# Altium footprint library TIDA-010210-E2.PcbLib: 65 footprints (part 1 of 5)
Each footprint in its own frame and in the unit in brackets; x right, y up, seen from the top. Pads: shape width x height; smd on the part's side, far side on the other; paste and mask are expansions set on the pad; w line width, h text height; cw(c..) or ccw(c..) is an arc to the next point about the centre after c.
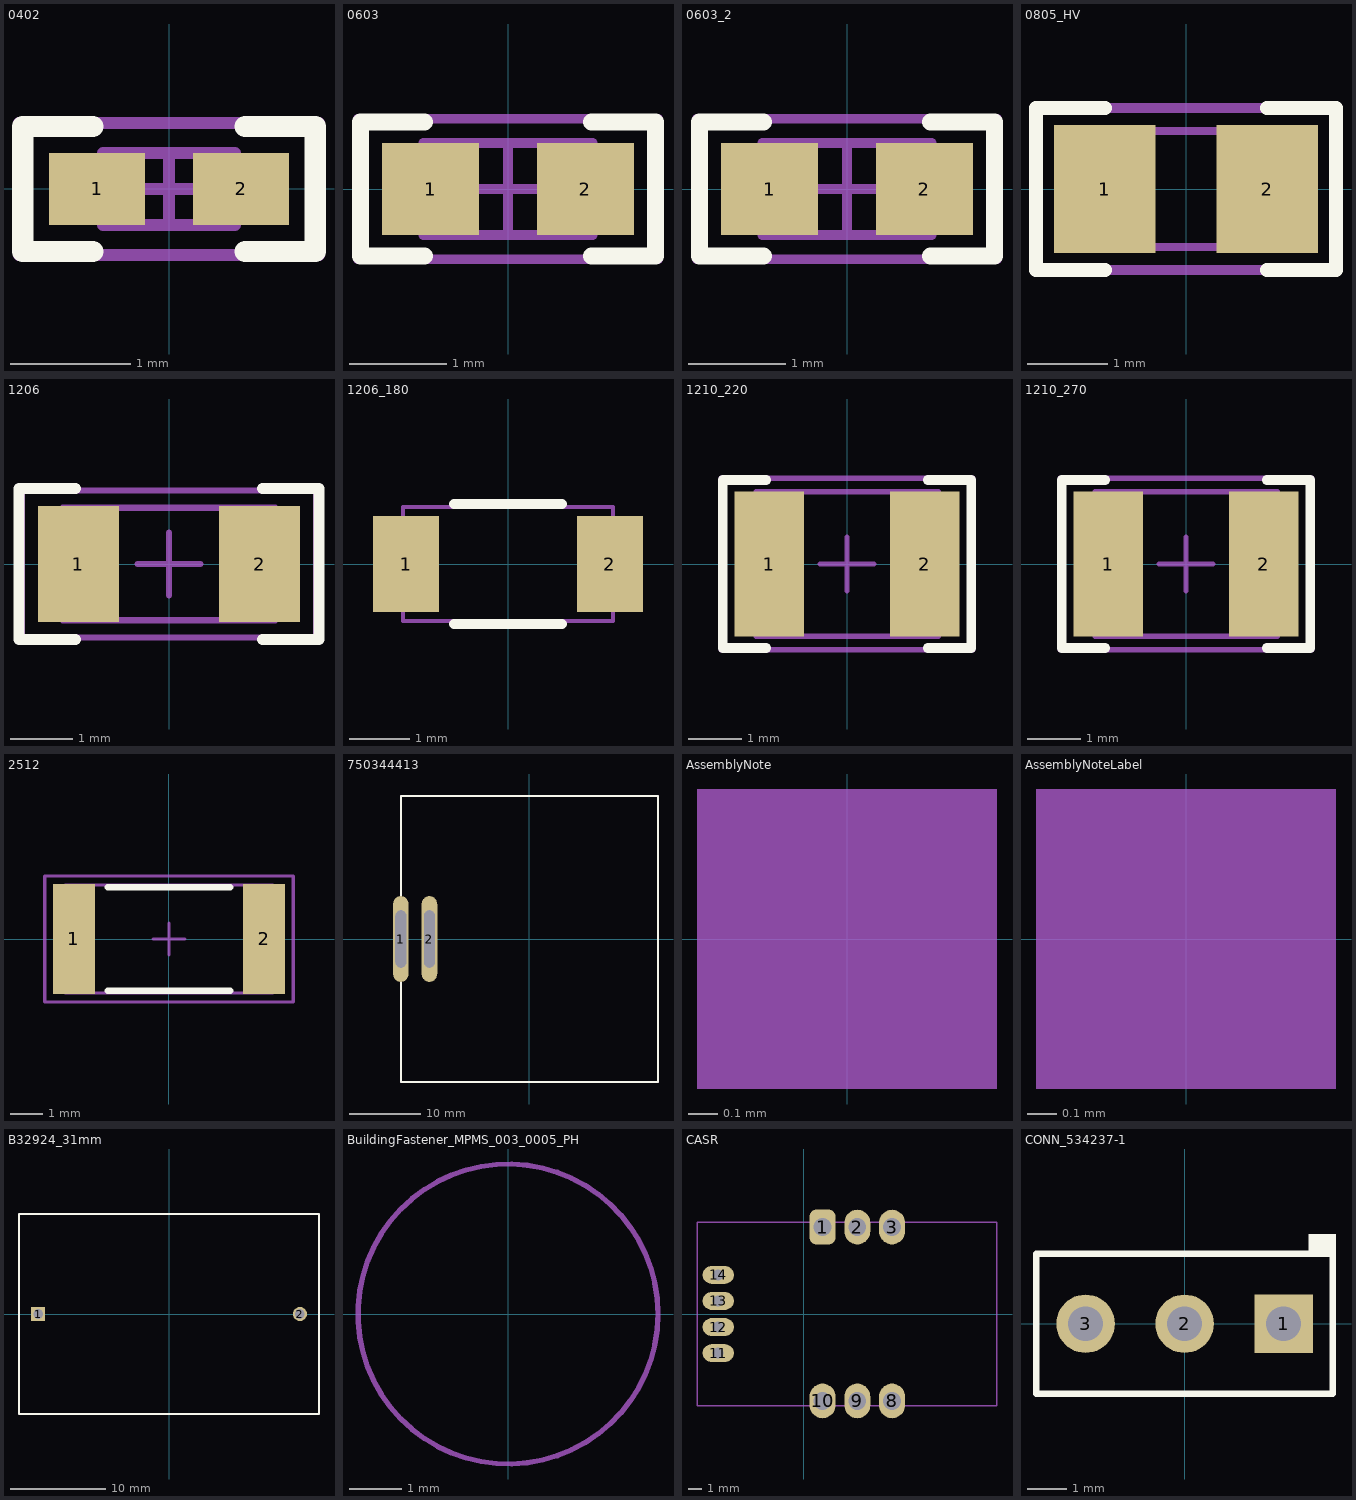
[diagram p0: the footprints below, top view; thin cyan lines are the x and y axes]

## 0402 [mm] "0402 from SM-752 data"
height 0.6
pads (2):
  rect 0.8x0.6 smd: 1(-0.6,0) 2(0.6,0)
Top Overlay:
  lines w0.178: -0.635,-0.521 -1.219,-0.521 -1.219,0.521 -0.635,0.521 ; 0.635,-0.521 1.219,-0.521 1.219,0.521 0.635,0.521
Mechanical 5:
  lines w0.1: -1.25,-0.55 1.25,-0.55 1.25,0.55 -1.25,0.55 -1.25,-0.55
  text ".Designator" at -1.117,-0.305 h0.61
Mechanical 13:
  lines w0.1: -0.35,-0.3 -0.35,0.3 ; 0.35,-0.3 0.35,0.3 ; -0.55,-0.3 -0.55,0.3 0.55,0.3 0.55,-0.3 -0.55,-0.3
Mechanical 15:
  lines w0.1: -0.3,0 0.3,0 ; 0,-0.3 0,0.3 ; -1.25,-0.55 -1.25,0.55 1.25,0.55 1.25,-0.55 -1.25,-0.55
3D body: height 0.6, standoff 0, extent -0.549,-0.299 -0.351,0.299
3D body: height 0.6, standoff 0, extent -0.349,-0.299 0.349,0.299
3D body: height 0.6, standoff 0, extent 0.351,-0.299 0.549,0.299

## 0603 [mm] "0603 from SM-752 data"
height 1
pads (2):
  rect 1x0.95 smd: 1(-0.8,0) 2(0.8,0)
Top Overlay:
  lines w0.178: -0.864,-0.691 -1.524,-0.691 -1.524,0.693 -0.864,0.693 ; 0.864,-0.691 1.524,-0.691 1.524,0.693 0.864,0.693
Mechanical 5:
  lines w0.1: -1.55,-0.725 -1.55,0.725 1.55,0.725 1.55,-0.725 -1.55,-0.725
  text ".Designator" at -1.397,-0.381 h0.76
Mechanical 13:
  lines w0.1: -0.55,-0.475 -0.55,0.475 ; 0.55,-0.475 0.55,0.475 ; -0.875,-0.475 0.875,-0.475 0.875,0.475 -0.875,0.475 -0.875,-0.475
Mechanical 15:
  lines w0.1: -0.475,0 0.475,0 ; 0,-0.475 0,0.475 ; -1.55,-0.725 1.55,-0.725 1.55,0.725 -1.55,0.725 -1.55,-0.725
3D body: height 1, standoff 0, extent -0.874,-0.474 -0.551,0.474
3D body: height 1, standoff 0, extent -0.549,-0.474 0.549,0.474
3D body: height 1, standoff 0, extent 0.551,-0.474 0.874,0.474

## 0603_2 [mm]
pads (2):
  rect 1x0.95 smd: 1(-0.8,0) 2(0.8,0)
Top Overlay:
  lines w0.178: -0.864,-0.691 -1.524,-0.691 -1.524,0.693 -0.864,0.693 ; 0.864,-0.691 1.524,-0.691 1.524,0.693 0.864,0.693
Mechanical 5:
  lines w0.1: -1.55,-0.725 -1.55,0.725 1.55,0.725 1.55,-0.725 -1.55,-0.725
  text ".Designator" at -1.397,-0.381 h0.76
Mechanical 13:
  lines w0.1: -0.55,-0.475 -0.55,0.475 ; 0.55,-0.475 0.55,0.475 ; -0.875,-0.475 0.875,-0.475 0.875,0.475 -0.875,0.475 -0.875,-0.475
Mechanical 15:
  lines w0.1: -0.475,0 0.475,0 ; 0,-0.475 0,0.475 ; -1.55,-0.725 1.55,-0.725 1.55,0.725 -1.55,0.725 -1.55,-0.725
3D body: height 1, standoff 0, extent -0.874,-0.474 -0.551,0.474
3D body: height 1, standoff 0, extent -0.549,-0.474 0.549,0.474
3D body: height 1, standoff 0, extent 0.551,-0.474 0.874,0.474

## 0805_HV [mil] "0805 with 30mil clearance between pads"
height 57.09
pads (2):
  rect 50x63 smd: 1(-40,0) 2(40,0)
Top Overlay:
  lines w7: -40,-40 -74,-40 -74,0 -74,40 -40,40 ; 40,-40 74,-40 74,0 74,40 40,40
Mechanical 5:
  lines w5: -74,-40 -74,40 74,40 74,-40 -74,-40
  text ".Designator" at -64,-17 h35
Mechanical 13:
  lines w3.94: -25.59,-28.54 -25.59,28.54 ; 25.59,-28.54 25.59,28.54 ; -43.31,-28.54 -43.31,28.54 43.31,28.54 43.31,-28.54 -43.31,-28.54
3D body: height 57.09, standoff 0, extent 25.61,-28.52 43.29,28.52
3D body: height 57.09, standoff 0, extent -25.57,-28.52 25.57,28.52
3D body: height 57.09, standoff 0, extent -43.29,-28.52 -25.61,28.52

## 1206 [mm] "1206 from SM-752 data"
height 1.35
pads (2):
  rect 1.3x1.85 smd: 1(-1.45,0) 2(1.45,0)
Top Overlay:
  lines w0.178: -1.5,-1.21 -2.4,-1.21 -2.4,1.21 -1.5,1.21 ; 1.5,-1.21 2.4,-1.21 2.4,1.21 1.5,1.21
Mechanical 5:
  lines w0.1: -1.7,-0.9 -1.7,0.9 1.7,0.9 1.7,-0.9 -1.7,-0.9
  text ".Designator" at -1.475,-0.4 h0.81
Mechanical 13:
  lines w0.1: -1.2,-0.9 -1.2,0.9 ; 1.2,-0.9 1.2,0.9 ; -1.7,-0.9 -1.7,0.9 1.7,0.9 1.7,-0.9 -1.7,-0.9
Mechanical 15:
  lines w0.1: -0.5,0 0.5,0 ; 0,-0.5 0,0.5 ; -2.35,-1.175 -2.35,1.175 2.35,1.175 2.35,-1.175 -2.35,-1.175
3D body: height 1.35, standoff 0, extent 1.201,-0.899 1.699,0.899
3D body: height 1.35, standoff 0, extent -1.199,-0.899 1.199,0.899
3D body: height 1.35, standoff 0, extent -1.699,-0.899 -1.201,0.899

## 1206_180 [mm] "1206_180"
height 1.8
pads (2):
  rect 1.1x1.6 smd: 1(-1.7,0) 2(1.7,0)
Top Overlay:
  lines w0.17: -0.9,-1 0.9,-1 ; -0.9,1 0.9,1
Mechanical 5:
  lines w0.07: -1.75,-0.95 1.75,-0.95 1.75,0.95 -1.75,0.95 -1.75,-0.95
  text ".Designator" at -1.5,-0.4 h0.81
3D body: height 1.8, standoff 0, extent -1.749,-0.949 -1.301,0.949
3D body: height 1.8, standoff 0, extent -1.299,-0.949 1.299,0.949
3D body: height 1.8, standoff 0, extent 1.301,-0.949 1.749,0.949

## 1210_220 [mm] "1210"
height 2.2
pads (2):
  rect 1.3x2.7 smd: 1(-1.45,0) 2(1.45,0)
Top Overlay:
  lines w0.178: -1.511,-1.568 -2.316,-1.568 -2.316,1.568 -1.511,1.568 ; 1.511,-1.568 2.316,-1.568 2.316,1.568 1.511,1.568
Mechanical 5:
  lines w0.1: -1.7,-1.35 -1.7,1.35 1.7,1.35 1.7,-1.35 -1.7,-1.35
  text ".Designator" at -1.4,-0.375 h0.76
Mechanical 13:
  lines w0.1: -1.2,-1.35 -1.2,1.35 ; 1.2,-1.35 1.2,1.35 ; -1.7,-1.35 1.7,-1.35 1.7,1.35 -1.7,1.35 -1.7,-1.35
Mechanical 15:
  lines w0.1: -0.5,0 0.5,0 ; 0,-0.5 0,0.5 ; -2.35,-1.6 2.35,-1.6 2.35,1.6 -2.35,1.6 -2.35,-1.6
3D body: height 2.2, standoff 0, extent 1.201,-1.349 1.699,1.349
3D body: height 2.2, standoff 0, extent -1.199,-1.349 1.199,1.349
3D body: height 2.2, standoff 0, extent -1.699,-1.349 -1.201,1.349

## 1210_270 [mm] "1210"
height 2.7
pads (2):
  rect 1.3x2.7 smd: 1(-1.45,0) 2(1.45,0)
Top Overlay:
  lines w0.178: -1.511,-1.568 -2.316,-1.568 -2.316,1.568 -1.511,1.568 ; 1.511,-1.568 2.316,-1.568 2.316,1.568 1.511,1.568
Mechanical 5:
  lines w0.1: -1.7,-1.35 1.7,-1.35 1.7,1.35 -1.7,1.35 -1.7,-1.35
  text ".Designator" at -1.4,-0.375 h0.76
Mechanical 13:
  lines w0.1: -1.2,-1.35 -1.2,1.35 ; 1.2,-1.35 1.2,1.35 ; -1.7,-1.35 -1.7,1.35 1.7,1.35 1.7,-1.35 -1.7,-1.35
Mechanical 15:
  lines w0.1: -0.5,0 0.5,0 ; 0,-0.5 0,0.5 ; -2.35,-1.6 -2.35,1.6 2.35,1.6 2.35,-1.6 -2.35,-1.6
3D body: height 2.7, standoff 0, extent -1.699,-1.349 -1.201,1.349
3D body: height 2.7, standoff 0, extent -1.199,-1.349 1.199,1.349
3D body: height 2.7, standoff 0, extent 1.201,-1.349 1.699,1.349

## 2512 [mm] "Chip Resistor, Body 6.3x3.2mm, IPC Medium Density"
height 0.71
pads (2):
  rect 1.3x3.4 smd: 1(-2.95,0) 2(2.95,0)
Top Overlay:
  lines w0.2: -1.9,-1.6 1.9,-1.6 ; -1.9,1.6 1.9,1.6
Mechanical 5:
  lines w0.1: -3.225,-1.675 3.225,-1.675 3.225,1.675 -3.225,1.675 -3.225,-1.675
  text ".Designator" at -1.85,-0.5 h1.02
Mechanical 13:
  lines w0.1: -2.463,-1.675 -2.463,1.675 ; 2.463,-1.675 2.463,1.675 ; -3.225,-1.675 3.225,-1.675 3.225,1.675 -3.225,1.675 -3.225,-1.675
Mechanical 15:
  lines w0.1: -0.5,0 0.5,0 ; 0,-0.5 0,0.5 ; -3.85,-1.95 3.85,-1.95 3.85,1.95 -3.85,1.95 -3.85,-1.95
3D body: height 0.71, standoff 0, extent -3.224,-1.674 -2.464,1.674
3D body: height 0.71, standoff 0, extent -2.462,-1.674 2.462,1.674
3D body: height 0.71, standoff 0, extent 2.464,-1.674 3.224,1.674

## 750344413 [mm] "Inductor, TH, 2-Leads, Body 36x40mm"
height 40
pads (2):
  oval 2.2x12 hole 1.5 slot 8 at 90 deg: 1(-18,0) 2(-14,0)
Top Overlay:
  lines w0.254: -18,-20 0,-20 18,-20 18,0 18,20 0,20 -18,20 -18,0 -18,-20
Mechanical 5:
  lines w0.254: -18,-20 -18,0 -18,20 0,20 18,20 18,0 18,-20 0,-20 -18,-20
  text ".Designator" at -0.301,-0.193 h0.46

## AssemblyNote [mm] "Assembly Note"
Mechanical 5:
  rectangle: -0.508,-0.508 0.508,0.508
  text ".Comment" at 1.143,-0.508 h0.64
  text ".Designator" at -4.191,-0.508 h0.64

## AssemblyNoteLabel [mm] "Assembly Note for PCB Labels"
Mechanical 5:
  rectangle: -0.508,-0.508 0.508,0.508
  text ".Designator" at -4.191,-0.508 h0.64
  text "Install label in silkscreened box after final wash.  Text shall be 8 pt font.  Text shall be per the Label Table in the PDF schematic." at 1.143,-0.508 h0.64

## B32924_31mm [mm] "Epcos film capacitors, 27.5mm spacing"
height 31
pads (2):
  rect 1.5x1.5 hole 1: 1(-13.75,0)
  round 1.5 hole 1: 2(13.75,0)
Top Overlay:
  lines w0.178: -15.75,-10.5 0,-10.5 15.75,-10.5 15.75,0 15.75,10.5 0,10.5 -15.75,10.5 -15.75,0 -15.75,-10.5
Mechanical 5:
  lines w0.127: -15.75,-10.5 -15.75,0 -15.75,10.5 0,10.5 15.75,10.5 15.75,0 15.75,-10.5 0,-10.5 -15.75,-10.5
  text ".Designator" at -1.524,-0.508 h1.02
3D body: height 31, standoff 0, extent -15.749,-10.499 15.749,10.499

## BuildingFastener_MPMS_003_0005_PH [mil] "MACHINE SCREW PAN PHILLIPS M3"
height 97.64
pads (1):
  round 1 on Mech3: 0(0,0)
Mechanical 5:
  circle w3.94: c0,0 r112.2
  text ".Designator" at -55.12,-15.75 h30
3D body "Screw_M3_MPMS 003 0005 PH.stp": height 92.82, standoff -196.25, extent -118.1,-118.1 118.12,118.12

## CASR [mm] "TH, 10-Leads, Body 13.4x21.91mm"
height 17
pads (10):
  rrect50% 1.9x2.54 hole 1.3: 1(1.37,6.35)
  oval 1.9x2.54 hole 1.3: 2(3.91,6.35) 3(6.45,6.35) 8(6.45,-6.35) 9(3.91,-6.35) 10(1.37,-6.35)
  oval 2.3x1.3 hole 0.8: 11(-6.25,-2.858) 12(-6.25,-0.953) 13(-6.25,0.952) 14(-6.25,2.857)
Mechanical 5:
  lines w0.1: -7.8,-6.7 -7.8,6.7 14.11,6.7 14.11,-6.7 -7.8,-6.7
  text ".Designator" at -1.7,-0.4 h1.02
3D body "CASR.stp": height 16.5, standoff -3.5, extent -7.8,-6.85 14.11,6.85

## CONN_534237-1 [mm] "TE Connectivity"
height 8.64
pads (3):
  rect 1.5x1.5 hole 0.889: 1(2.54,0)
  round 1.5 hole 0.889: 2(0,0) 3(-2.54,0)
Top Overlay:
  rectangle: 3.185,1.8 3.885,2.3
  lines w0.17: -3.8,-1.8 3.8,-1.8 3.8,1.8 -3.8,1.8 -3.8,-1.8
Mechanical 5:
  lines w0.1: -3.81,-1.778 3.81,-1.778 3.81,1.778 -3.81,1.778 -3.81,-1.778
  text ".Designator" at -1.9,-0.5 h1.02
3D body: height 8.65, standoff 8, extent 1.941,-0.449 3.139,0.449
3D body: height 8.65, standoff 8, extent -0.599,-0.449 0.599,0.449
3D body: height 8.65, standoff 8, extent -3.139,-0.449 -1.941,0.449
3D body: height 1, standoff -2.9, extent 2.241,-0.199 2.839,0.199
3D body: height 1, standoff -2.9, extent -0.299,-0.199 0.299,0.199
3D body: height 8.64, standoff 0, extent -3.809,-1.777 3.809,1.777
3D body: height 1, standoff -2.9, extent -2.839,-0.199 -2.241,0.199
